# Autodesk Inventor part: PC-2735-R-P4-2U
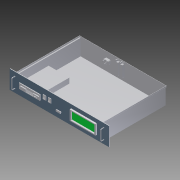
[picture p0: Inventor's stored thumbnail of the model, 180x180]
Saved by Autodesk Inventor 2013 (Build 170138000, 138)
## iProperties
Created: 2006-02
Part Number: PC-2735-R-P4-2U
Document SubType Name: Modeling
Designer: Autodesk, Inc.
Mass: 847.729 g
Surface Area: 5832.33 cm^2
Volume: 847.729 cm^3
Density: 1 g/cm^3
Material: Allgemein
Translation Standard: STEP AP214DIS
File Name: C:\My Documents\My Inventor\Projects\R11 Samples\Samples\Models\Assemblies\Test Station\Components\Purchased Components\PC, RACK MOUNT, 2U.stp
Preprocessor: Autodesk Inventor 10
Postprocessor: Build: 272, Release: 10 SP3a - Date: Thu 12/15/2005
Sent Units: INCHES
Uncertainty: 0.00039370078740199997
Author: Autodesk, Inc.
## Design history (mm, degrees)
feature "Base1"
body "Solid1"
